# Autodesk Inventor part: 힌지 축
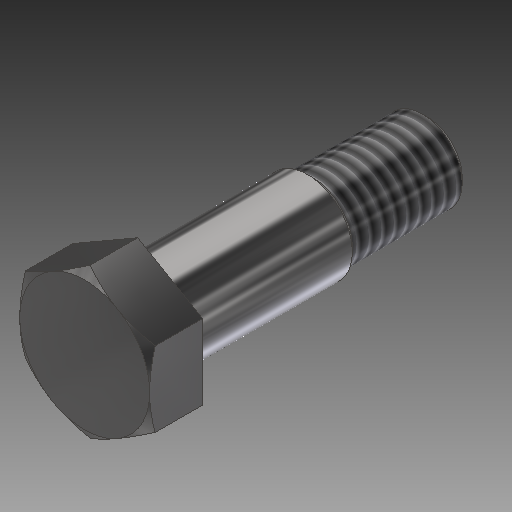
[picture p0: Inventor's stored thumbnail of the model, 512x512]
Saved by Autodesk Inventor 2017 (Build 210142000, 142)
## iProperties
Created: 2019-09
Part Number: 힌지 축
Material: 스테인리스강
Document SubType Name: Modeling
Designer: mduedu
Density: 1 g/cm^3
Appearance: 반광택
Author: mduedu
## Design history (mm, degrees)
sketch "스케치1"
  geometry: C1 r 4 at (0, 0); 1 further point
  constraints: 1 centre point, 1 coincident
  dimensions: "d0" = 8 diameter of C1
extrude "돌출1" new body sketch "스케치1" distance "d1" = 29; taper "d2" = 0 deg
sketch "스케치2"
  geometry: C1 r 4.5 at (0, 0); 1 further point
  constraints: 1 centre point, 1 coincident
  dimensions: "d3" = 9 diameter of C1
extrude "돌출2" join sketch "스케치2" distance "d4" = 17.5; taper "d5" = 0 deg
sketch "스케치3"
  geometry: L1 (0, 7.506)-(6.5, 3.753); L2 (6.5, 3.753)-(6.5, -3.753); L3 (6.5, -3.753)-(0, -7.506); L4 (0, -7.506)-(-6.5, -3.753); L5 (-6.5, -3.753)-(-6.5, 3.753); L6 (-6.5, 3.753)-(0, 7.506); C1 r 6.5 at (0, 0); 2 further points
  constraints: 12 end point, 2 coincident, 1 centre point, 1 tangent, 1 vertical alignment, 13 other
  dimensions: "d6" = 6.5 radius of C1
extrude "돌출3" join sketch "스케치3" distance "d8" = 5.3; taper "d9" = 0 deg
sketch "스케치4"
  geometry: L1 (-4, 11.5)-(-4.5, 11.5) reference; L2 (-4.5, 11.5)-(-4.5, 29) reference; L3 (-4.5, 29)-(-7.506, 29) reference; L4 (-7.506, 29)-(-7.506, 34.3) reference; L5 (-7.506, 34.3)-(7.506, 34.3) reference; L6 (7.506, 34.3)-(7.506, 29) reference; L7 (7.506, 29)-(4.5, 29) reference; L8 (4.5, 29)-(4.5, 11.5) reference; L9 (4.5, 11.5)-(4, 11.5) reference; L10 (4, 11.5)-(4, 0) reference; L11 (4, 0)-(-4, 0) reference; L12 (-4, 0)-(-4, 11.5) reference; L13 (0, 0)-(0, 34.3); L14 (7.506, 34.3)-(7.506, 33.746); L15 (6.506, 34.3)-(7.506, 33.746); L16 (7.506, 34.3)-(6.506, 34.3); L17 (4.5, 29)-(4, 29); L18 (4, 29)-(4, 28.5); L19 (4, 28.5)-(4.5, 28.5); L20 (4.5, 28.5)-(4.5, 29)
  constraints: 16 end point, 2 parallel, 2 perpendicular, 2 point on line, 1 horizontal, 1 midpoint
  dimensions: "d10" = 1 distance of L5.end L15.start; "d11" = 29 deg angle of L15 L5; "d12" = 0.5 distance of L19.end L7.end; "d13" = 0.5 distance of L18.end L19.end
revolve "회전1" sketch "스케치4" stored, may be unused: angle "d14" = 90 deg
feature "스레드1" dims "d15" = 10, "d16" = 0
chamfer "모따기1" distance "d17" = 0.5; stored, may be unused: second distance "d18" = 2, angle "d19" = 45 deg
chamfer "모따기2" distance "d20" = 0.5; stored, may be unused: second distance "d21" = 2, angle "d22" = 45 deg
node "솔리드1"
node "절단 모서리 투영1"
